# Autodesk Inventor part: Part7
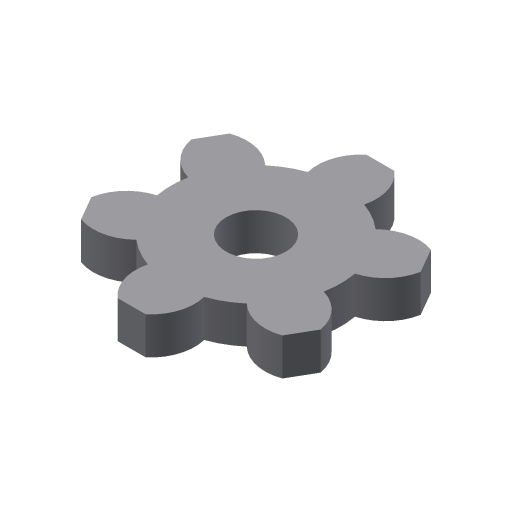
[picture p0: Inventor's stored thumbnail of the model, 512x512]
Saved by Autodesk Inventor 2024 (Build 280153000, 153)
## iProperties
Shininess: 77.0
Angle Display Precision: 2
Document Length Units: 11269
Document Angle Units: 11279
Document Time Units: 11290
Document Mass Units: 11283
Document Length Units Precision: 3
Document Angle Units Precision: 2
Created: 2002-01
Part Number: Part7
Document SubType Name: Modeling
Designer: ***
Density: 1 g/cm^3
Material: Generic
Appearance: Default
Density: 0.0
Volumn: 0.0
Area: 0.0
PropertySet Name: Model Information
Control State: 0
Master: False
Checked Out: False
Author: ***
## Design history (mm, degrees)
sketch "Sketch1"
  geometry: L1 (-3.771, 33.333)-(3.771, 33.333); L2 (-30.753, 13.401)-(-26.982, 19.933); L3 (-30.753, -13.401)-(-26.982, -19.933); L4 (-3.771, -33.333)-(3.771, -33.333); L5 (30.753, 13.401)-(26.982, 19.933); L6 (30.753, -13.401)-(26.982, -19.933); C1 r 8 at (0, 0); A1 r 11.863 centre (3.952, 24.328) between (-3.771, 33.333) and (-7.559, 21.457); A2 r 11.863 centre (-3.952, 24.328) between (7.559, 21.457) and (3.771, 33.333); A3 r 11.863 centre (-19.093, 15.587) between (-30.753, 13.401) and (-22.362, 4.182); A4 r 11.863 centre (-23.045, 8.742) between (-14.803, 17.275) and (-26.982, 19.933); A5 r 22.749 centre (0, 0) between (-7.559, 21.457) and (-14.803, 17.275); A6 r 11.863 centre (-23.045, -8.742) between (-26.982, -19.933) and (-14.803, -17.275); A7 r 11.863 centre (-19.093, -15.587) between (-22.362, -4.182) and (-30.753, -13.401); A8 r 11.863 centre (3.952, -24.328) between (-7.559, -21.457) and (-3.771, -33.333); A9 r 11.863 centre (-3.952, -24.328) between (3.771, -33.333) and (7.559, -21.457); A10 r 11.863 centre (23.045, 8.742) between (26.982, 19.933) and (14.803, 17.275); A11 r 11.863 centre (19.093, 15.587) between (22.362, 4.182) and (30.753, 13.401); A12 r 11.863 centre (19.093, -15.587) between (30.753, -13.401) and (22.362, -4.182); A13 r 11.863 centre (23.045, -8.742) between (14.803, -17.275) and (26.982, -19.933); A14 r 22.749 centre (0, 0) between (-22.362, 4.182) and (-22.362, -4.182); A15 r 22.749 centre (0, 0) between (-14.803, -17.275) and (-7.559, -21.457); A16 r 22.749 centre (0, 0) between (7.559, -21.457) and (14.803, -17.275); A17 r 22.749 centre (0, 0) between (22.362, -4.182) and (22.362, 4.182); A18 r 22.749 centre (0, 0) between (14.803, 17.275) and (7.559, 21.457)
  constraints: 36 point on circle, 19 centre point, 12 end point, 1 coincident
  dimensions: "d2" = 16 diameter of C1
extrude "Extrusion1" new body sketch "Sketch1" distance "d0" = 10; taper "d1" = 0 deg
body "Solid1"
